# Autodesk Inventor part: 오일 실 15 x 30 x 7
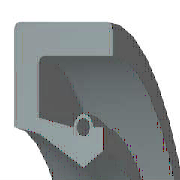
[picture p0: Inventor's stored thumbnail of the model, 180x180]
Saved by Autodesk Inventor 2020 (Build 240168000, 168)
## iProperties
Created: 2012-02
Part Number: 오일 실 15 x 30 x 7
Material: 고무
Description: 오일-실
Document SubType Name: Modeling
Standard: KS B 2804
Designer: mduedu
Standards Organization: KS
Language: ko-KR
Size Designation: S - 15 25 7
Categories: <MemberInstance><Categories><Category DisplayName="샤프트 부품" InternalName="7f7aeb1f-a693-4053-b835-cee3144e0d98" Mnemonic="SHFT"><Category DisplayName="실링" Intern
Density: 0.93 g/cm^3
Appearance: 고무 - 검은색 - 버전 1.1
IsCustomPart: 1
Author: mduedu
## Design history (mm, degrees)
revolve "본체" stored, may be unused: angle "d17" = 90 deg
revolve "스프링1" stored, may be unused: angle "d18" = 90 deg
body "Solid1"
sketch "스케치1"
  geometry: L1 (0, 15)-(7, 15); L2 (7, 15)-(7, 13.75); L3 (7, 13.75)-(1.75, 13.75); L4 (0, 15)-(0, 9.6); L5 (0, 9.6)-(1.75, 9.25); L6 (1.75, 9.25)-(4.9, 7.5); L7 (4.9, 7.5)-(0, 7.5); L8 (6.3, 8.375)-(6.3, 9.6); L9 (0, 0)-(9.586, 0) reference; L10 (4.9, 7.5)-(6.3, 8.375); L11 (0, 15)-(0, -2.5) reference; L12 (-1.917, 0)-(11.503, 0) reference; L13 (4.2, 9.6)-(1.75, 10.09); L14 (1.75, 10.09)-(1.75, 13.75); L15 (6.3, 9.6)-(5.6, 9.6); C1 r 0.455 at (4.9, 9.6); A1 r 0.7 centre (4.9, 9.6) between (5.6, 9.6) and (4.2, 9.6)
  constraints: 26 end point, 5 horizontal alignment, 4 perpendicular, 2 centre point, 2 collinear, 2 horizontal, 2 parallel, 2 point on circle, 2 point on line, 2 vertical alignment, 1 coincident
  dimensions: "d0" = 30 diameter of L1 L9 (= SD2); "d1" = 16.75 diameter of L8.start L9 (= ABDM); "d2" = 1.25 distance of L1.end L2.end (computed from SD); "d3" = 0.91 diameter of C1 (= SPDI); "d4" = 1.4 diameter of A1 (= SPDA); "d5" = 15 diameter of L6.end L9 (= NND); "d6" = 18.5 diameter of L5.end L9 (= TKDM); "d7" = 19.2 diameter of L4.end L9 (= HLDM); "d8" = 4.9 distance from line of C1.centre L4 (= SPDST); "d9" = 6.3 distance between parallel lines of L8 L4 (= SDI); "d10" = 7 distance between parallel lines of L2 L4 (= SWDT); "d12" = 1.75 distance between parallel lines of L14 L4 (= SD)
fillet "모깎기1" dims "d11" = 0.5 (= RR)
other parameters: "SD2" = 30 [user parameter; used in 1 equation term], "SWDT" = 7 [user parameter; used in 1 equation term], "RR" = 0.5 [user parameter; used in 1 equation term], "SD" = 1.75 [user parameter; used in 2 equation terms], "NND" = 15 [user parameter; used in 1 equation term], "SPDA" = 1.4 [user parameter; used in 1 equation term], "SPDI" = 0.91 [user parameter; used in 1 equation term], "TKDM" = 18.5 [user parameter; used in 1 equation term], "HLDM" = 19.2 [user parameter; used in 1 equation term], "ABDM" = 16.75 [user parameter; used in 1 equation term], "SDI" = 6.3 [user parameter; used in 1 equation term], "SPDST" = 4.9 [user parameter; used in 1 equation term], "d13" = 0, "d14" = 0, "d15" = 0, "LAB" = 0.35 [user parameter]
